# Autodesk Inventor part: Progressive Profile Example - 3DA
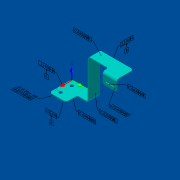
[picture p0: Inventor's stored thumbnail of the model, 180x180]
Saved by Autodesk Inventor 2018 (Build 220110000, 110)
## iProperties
Created: 2009-04
Part Number: Progressive Profile Example - 3DA
Document SubType Name: Modeling
Designer: Bryan Fischer
Density: 1 g/cm^3
Material: Generic
Appearance: Default(1)
Mass: 15.3329 g
Surface Area: 164.863 cm^2
Volume: 15.3329 cm^3
Author: Bryan Fischer
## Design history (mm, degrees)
node "Annotations"
  node "Leader Text 1"
  node "General Note 1"
node "Tolerance Features"
  node "Planar Surface 1" dims "d45" = 2.02685 (derived), "d46" = 4.2842 (derived), "d47" = 0.254 (derived), "d48" = 0 (derived), "d49" = 0 (derived), "d50" = 6.90047 (derived), "d51" = 9.77977 (derived), "d52" = 0.254 (derived), "d53" = 0 (derived), "d54" = 0 (derived), "d55" = 3.81008 (derived), "d56" = 4.20965 (derived), "d57" = 0.254 (derived), "d58" = 0 (derived), "d59" = 0 (derived), "d60" = 2.77754 (derived), "d61" = 1.02195 (derived), "d62" = 0.762 (derived), "d63" = 0 (derived), "d64" = 0 (derived), "d81" = 0 (derived), "d83" = 0.508 (derived), "d84" = 0 (derived), "d85" = 0 (derived)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
  node "Datum Reference Frame 1"
  node "Planar Surface 2" dims "d45" = 2.02685 (derived), "d46" = 4.2842 (derived), "d47" = 0.254 (derived), "d48" = 0 (derived), "d49" = 0 (derived), "d50" = 6.90047 (derived), "d51" = 9.77977 (derived), "d52" = 0.254 (derived), "d53" = 0 (derived), "d54" = 0 (derived), "d55" = 3.81008 (derived), "d56" = 4.20965 (derived), "d57" = 0.254 (derived), "d58" = 0 (derived), "d59" = 0 (derived), "d60" = 2.77754 (derived), "d61" = 1.02195 (derived), "d62" = 0.762 (derived), "d63" = 0 (derived), "d64" = 0 (derived), "d81" = 0 (derived), "d83" = 0.508 (derived), "d84" = 0 (derived), "d85" = 0 (derived)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
  node "Datum Reference Frame 2"
  node "Planar Surface 3" dims "d45" = 2.02685 (derived), "d46" = 4.2842 (derived), "d47" = 0.254 (derived), "d48" = 0 (derived), "d49" = 0 (derived), "d50" = 6.90047 (derived), "d51" = 9.77977 (derived), "d52" = 0.254 (derived), "d53" = 0 (derived), "d54" = 0 (derived), "d55" = 3.81008 (derived), "d56" = 4.20965 (derived), "d57" = 0.254 (derived), "d58" = 0 (derived), "d59" = 0 (derived), "d60" = 2.77754 (derived), "d61" = 1.02195 (derived), "d62" = 0.762 (derived), "d63" = 0 (derived), "d64" = 0 (derived), "d81" = 0 (derived), "d83" = 0.508 (derived), "d84" = 0 (derived), "d85" = 0 (derived)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
  node "Datum Reference Frame 3"
  node "Planar Surface 4"
  node "Parallel Axes Pattern 1"
  node "Planar Surface 5"
  node "Planar Surface 6"
  node "Extruded Group 1"
  node "General Group 1"
sketch "Sketch1"
  geometry: L1 (0, 0)-(63.5, 0); L2 (63.5, 0)-(63.5, 88.9); L3 (63.5, 88.9)-(139.7, 88.9); L4 (0, 2.032)-(61.468, 2.032); L5 (61.468, 2.032)-(61.468, 90.932); L6 (61.468, 90.932)-(139.7, 90.932); L7 (139.7, 88.9)-(139.7, 90.932); L8 (0, 0)-(0, 2.032)
  constraints: 16 end point, 3 parallel, 3 perpendicular, 1 horizontal, 2 other
  dimensions: "d0" = 63.5 distance of L1.start L1.end; "d1" = 88.9 distance of L1.end L2.end; "d2" = 76.2 distance of L2.end L3.end; "d3" = 2.032 distance between parallel lines of L1 L4
extrude "Extrusion1" new body sketch "Sketch1" distance "d4" = 25.4; taper "d5" = 0 deg
sketch "Sketch2"
  geometry: L1 (0, 0)-(0, 2.032) reference; L2 (63.5, 0)-(0, 0) reference; L3 (0, 2.032)-(38.1, 2.032); L4 (38.1, 2.032)-(38.1, 0); L5 (38.1, 0)-(0, 0); L6 (0, 0)-(0, 2.032)
  constraints: 8 end point, 2 parallel, 1 horizontal, 1 perpendicular, 1 point on line
  dimensions: "d6" = 38.1 distance of L4.end L5.end
extrude "Extrusion2" join sketch "Sketch2" distance "d7" = 25.4; taper "d8" = 0 deg
sketch "Sketch3"
  geometry: L1 (-25.4, 2.032)-(-25.4, 0) reference; L2 (0, 0)-(-25.4, 0) reference; L3 (0, 0)-(0, 2.032) reference; L4 (-38.1, 2.032)-(-38.1, -23.368); L5 (-38.1, -23.368)-(-36.068, -23.368); L6 (-36.068, -23.368)-(-36.068, 0); L7 (-25.4, 2.032)-(-38.1, 2.032); L8 (-25.4, 0)-(-36.068, 0)
  constraints: 11 end point, 3 parallel, 3 perpendicular
  dimensions: "d9" = 25.4 distance of L4.start L4.end; "d10" = 2.032 distance between parallel lines of L4 L6 (= d3); "d12" = 38.1 distance between parallel lines of L4 L3
extrude "Extrusion3" join sketch "Sketch3" distance "d13" = 31.75; taper "d14" = 0 deg
fillet "Fillet1" dims "d15" = 4.064 (= 2 x d3)
fillet "Fillet2" dims "d16" = 6.096 (= 3 x d3)
sketch "Sketch4"
  geometry: L1 (-36.068, -25.4)-(-10.16, -25.4) reference; L2 (-42.164, 19.304)-(-42.164, -19.304) reference; 2 further points
  constraints: 1 vertical alignment
  dimensions: "d17" = 12.7 distance from line of point (-29.464, -12.7) L1; "d18" = 12.7 distance from line of point (-29.464, -12.7) L2 (= d17); "d19" = 25.4 distance of point (-29.464, 12.7) point (-29.464, -12.7)
hole "Hole1" sketch "Sketch4" at (-29.464, -12.7), (-29.464, 12.7) diameter "d20" = 7.1374; stored, may be unused: countersink angle "d24" = 82 deg, drill point angle "d26" = 118 deg; dims "d21" = 12.7, "d22" = 9.525, "d23" = 6.35, "d25" = 19.05
sketch "Sketch5"
  geometry: L1 (-31.75, 13.208)-(0, 13.208) reference; L2 (-6.096, -6.096)-(-25.654, -6.096) reference; L3 (-15.875, -6.096)-(-15.875, 13.208); L4 (-23.495, 4.778)-(-8.255, 4.778); L5 (-23.495, 0.81)-(-8.255, 0.81); A1 r 1.984 centre (-23.495, 2.794) between (-23.495, 4.778) and (-23.495, 0.81); A2 r 1.984 centre (-8.255, 2.794) between (-8.255, 0.81) and (-8.255, 4.778); 2 further points
  constraints: 6 end point, 4 point on circle, 4 tangent, 2 centre point, 2 coincident, 2 midpoint, 1 horizontal
  dimensions: "d27" = 7.62 distance from line of L3 point (-23.495, 2.794); "d28" = 7.62 distance from line of point (-8.255, 2.794) L3 (= d27); "d29" = 8.89 distance from line of point (-8.255, 2.794) L2; "d37" = 3.96875 diameter of A1; "d38" = 3.96875 diameter of A2 (= d37)
extrude "Extrusion4" cut sketch "Sketch5" extent not by distance; stored distance "d39" = 25.4; taper "d40" = 0 deg
workplane "Work Plane1"
workplane "Work Plane4"
workplane "Work Plane5"
workpoint "Work Point1"
  workaxis "Work Axis3"
  workaxis "Work Axis4"
body "Solid1"
node "Feature Control Frame 1"
node "Datum Identifier 1" dims "d2" = 76.2, "d45" = 2.02685 (derived), "d46" = 4.2842 (derived), "d47" = 0.254 (derived), "d48" = 0 (derived), "d49" = 0 (derived), "d50" = 6.90047 (derived), "d51" = 9.77977 (derived), "d52" = 0.254 (derived), "d53" = 0 (derived), "d54" = 0 (derived), "d55" = 3.81008 (derived), "d56" = 4.20965 (derived), "d57" = 0.254 (derived), "d58" = 0 (derived), "d59" = 0 (derived), "d60" = 2.77754 (derived), "d61" = 1.02195 (derived), "d62" = 0.762 (derived), "d63" = 0 (derived), "d64" = 0 (derived), "d81" = 0 (derived), "d83" = 0.508 (derived), "d84" = 0 (derived)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
node "Feature Control Frame 2"
node "Datum Identifier 2" dims "d2" = 76.2, "d45" = 2.02685 (derived), "d46" = 4.2842 (derived), "d47" = 0.254 (derived), "d48" = 0 (derived), "d49" = 0 (derived), "d50" = 6.90047 (derived), "d51" = 9.77977 (derived), "d52" = 0.254 (derived), "d53" = 0 (derived), "d54" = 0 (derived), "d55" = 3.81008 (derived), "d56" = 4.20965 (derived), "d57" = 0.254 (derived), "d58" = 0 (derived), "d59" = 0 (derived), "d60" = 2.77754 (derived), "d61" = 1.02195 (derived), "d62" = 0.762 (derived), "d63" = 0 (derived), "d64" = 0 (derived), "d81" = 0 (derived), "d83" = 0.508 (derived), "d84" = 0 (derived)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
node "Feature Control Frame 3"
node "Datum Identifier 3" dims "d2" = 76.2, "d45" = 2.02685 (derived), "d46" = 4.2842 (derived), "d47" = 0.254 (derived), "d48" = 0 (derived), "d49" = 0 (derived), "d50" = 6.90047 (derived), "d51" = 9.77977 (derived), "d52" = 0.254 (derived), "d53" = 0 (derived), "d54" = 0 (derived), "d55" = 3.81008 (derived), "d56" = 4.20965 (derived), "d57" = 0.254 (derived), "d58" = 0 (derived), "d59" = 0 (derived), "d60" = 2.77754 (derived), "d61" = 1.02195 (derived), "d62" = 0.762 (derived), "d63" = 0 (derived), "d64" = 0 (derived), "d81" = 0 (derived), "d83" = 0.508 (derived), "d84" = 0 (derived)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
node "Feature Control Frame 4"
node "Simple Hole 1"
node "Simple Hole 2"
node "Hole Note 1" dims "d2" = 76.2
node "Feature Control Frame 5"
node "Feature Control Frame 6"
node "Planar Surface 7"
node "Cylindrical Surface 1"
node "Planar Surface 8"
node "Cylindrical Surface 2"
node "Feature Control Frame 8"
node "Feature Control Frame 7"
node "Planar Surface 9"
node "Cylindrical Surface 3"
node "Planar Surface 10"
node "Cylindrical Surface 4"
node "Cylindrical Surface 5"
node "Planar Surface 11"
node "Cylindrical Surface 6"
node "Planar Surface 12"
node "Cylindrical Surface 7"
node "Planar Surface 13"
node "Cylindrical Surface 8"
node "Planar Surface 14"
node "Cylindrical Surface 9"
node "Feature Control Frame 10"
node "General Surface Profile Tolerance"
other parameters: "d41" = 0, "d43" = 90 deg, "d44" = 90 deg, "d65" = 0, "d66" = 0, "d67" = 0, "d68" = 0, "d69" = 0, "d70" = 0
